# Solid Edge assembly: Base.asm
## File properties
Author: nakano
Template: iso metric assembly.asm
Last saved by: nakano
Revision: 12
Application: Solid Edge
Username: nakano
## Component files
Base BR-KT.par
hitec hs485-hb.asm
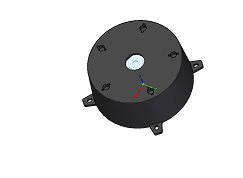
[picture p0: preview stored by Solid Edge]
